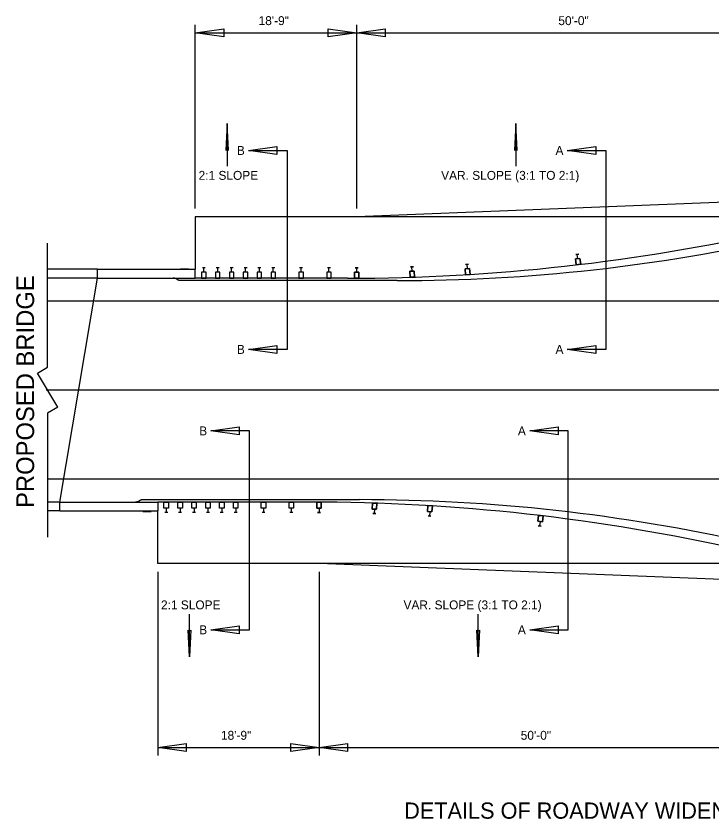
# Model space of a CAD drawing. Extents: x -149 to 1228740, y -106 to 152440.
# Drawn here: x -124.69 to -81.77, y -103.1 to -53.6 of the extents above; entities that cross this region are included whole.
import ezdxf

# ---------------------------------------------------------------- set-up
doc = ezdxf.new("R2010")
doc.units = 0
for name, color, linetype in [('B_Concrete', 7, 'Continuous'), ('R_Annotation', 7, 'Continuous'), ('R_Centerline', 7, 'Continuous'), ('R_Dimension', 7, 'Continuous'), ('R_Proposed Road', 7, 'Continuous'), ('R_Proposed Road_Lane', 7, 'Continuous'), ('R_Proposed Road_Shoulder', 7, 'Continuous')]:
    doc.layers.add(name, color=color, linetype=linetype)

msp = doc.modelspace()

# ---------------------------------------------------------------- linework, layer by layer
at = {"layer": 'B_Concrete'}
for p, q in [((-119.665, -69.21), (-122.739, -69.21)), ((-119.665, -69.21), (-113.633, -69.21)), ((-114.546, -69.181), (-114.044, -69.181)), ((-114.546, -69.181), (-114.546, -69.21)), ((-114.501, -69.181), (-114.501, -69.21)), ((-114.455, -69.181), (-114.455, -69.21)), ((-114.135, -69.181), (-114.135, -69.21)), ((-114.089, -69.181), (-114.089, -69.21)), ((-114.044, -69.181), (-114.044, -69.21)), ((-113.633, -69.758), (-113.633, -69.21)), ((-119.665, -69.758), (-122.739, -69.758)), ((-119.665, -69.758), (-113.633, -69.758)), ((-121.986, -83.56), (-122.739, -83.56)), ((-121.986, -83.56), (-115.953, -83.56)), ((-115.953, -83.56), (-115.953, -84.108)), ((-121.986, -84.108), (-122.739, -84.108)), ((-121.986, -84.108), (-115.953, -84.108)), ((-116.867, -84.137), (-116.867, -84.108)), ((-116.867, -84.137), (-116.364, -84.137)), ((-116.821, -84.137), (-116.821, -84.108)), ((-116.776, -84.137), (-116.776, -84.108)), ((-116.456, -84.137), (-116.456, -84.108)), ((-116.41, -84.137), (-116.41, -84.108)), ((-116.364, -84.137), (-116.364, -84.108))]:
    msp.add_line(p, q, dxfattribs=at)
for points in [[(-119.665, -69.758), (-119.665, -69.21)], [(-119.665, -69.758), (-119.665, -69.21)], [(-121.986, -83.56), (-119.665, -69.758)], [(-121.986, -84.108), (-121.986, -83.56)], [(-121.986, -84.108), (-121.986, -83.56)]]:
    msp.add_lwpolyline(points, dxfattribs=at)
at = {"layer": 'R_Annotation'}
for p, q in [((-111.675, -60.214), (-111.675, -62.856)), ((-93.874, -60.214), (-93.874, -62.856)), ((-122.739, -75.247), (-122.739, -67.588)), ((-123.361, -75.606), (-122.739, -75.247)), ((-122.117, -77.711), (-123.361, -75.606)), ((-122.117, -77.711), (-122.739, -78.07)), ((-122.739, -78.07), (-122.739, -85.73)), ((-113.996, -93.105), (-113.996, -90.463)), ((-96.195, -93.105), (-96.195, -90.463))]:
    msp.add_line(p, q, dxfattribs=at)
for points in [[(-111.675, -60.214), (-111.757, -61.859), (-111.675, -61.813), (-111.593, -61.859)], [(-93.874, -60.214), (-93.957, -61.859), (-93.874, -61.813), (-93.792, -61.859)], [(-113.996, -93.105), (-114.078, -91.459), (-113.996, -91.505), (-113.913, -91.459)], [(-96.195, -93.105), (-96.277, -91.459), (-96.195, -91.505), (-96.113, -91.459)]]:
    msp.add_lwpolyline(points, close=True, dxfattribs=at)
at = {"layer": 'R_Centerline'}
msp.add_line((-40.54, -76.659), (-122.83, -76.659), dxfattribs=at)
at = {"layer": 'R_Dimension'}
for p, q in [((-113.633, -65.465), (-113.633, -54.129)), ((-103.681, -65.465), (-103.681, -54.129)), ((-113.633, -54.629), (-103.681, -54.629)), ((-103.681, -54.629), (-76.262, -54.629)), ((-113.633, -61.99), (-113.633, -58.2)), ((-115.953, -87.853), (-115.953, -99.189)), ((-106.002, -87.853), (-106.002, -99.189)), ((-115.953, -92.394), (-115.953, -96.185)), ((-115.953, -98.689), (-106.002, -98.689)), ((-106.002, -98.689), (-78.582, -98.689))]:
    msp.add_line(p, q, dxfattribs=at)
for points in [[(-111.883, -54.879), (-113.633, -54.629), (-111.883, -54.379)], [(-105.431, -54.379), (-103.681, -54.629), (-105.431, -54.879)], [(-101.931, -54.879), (-103.681, -54.629), (-101.931, -54.379)], [(-108.602, -62.133), (-110.352, -61.883), (-108.602, -61.633)], [(-88.943, -62.133), (-90.693, -61.883), (-88.943, -61.633)], [(-108.602, -74.398), (-110.352, -74.148), (-108.602, -73.898)], [(-88.943, -74.398), (-90.693, -74.148), (-88.943, -73.898)], [(-110.923, -79.421), (-112.673, -79.171), (-110.923, -78.921)], [(-91.264, -79.421), (-93.014, -79.171), (-91.264, -78.921)], [(-110.923, -91.685), (-112.673, -91.435), (-110.923, -91.185)], [(-91.264, -91.685), (-93.014, -91.435), (-91.264, -91.185)], [(-114.203, -98.939), (-115.953, -98.689), (-114.203, -98.439)], [(-107.752, -98.439), (-106.002, -98.689), (-107.752, -98.939)], [(-104.252, -98.939), (-106.002, -98.689), (-104.252, -98.439)]]:
    msp.add_lwpolyline(points, close=True, dxfattribs=at)
for points in [[(-110.352, -61.883), (-107.972, -61.883), (-107.972, -74.148), (-110.352, -74.148)], [(-90.693, -61.883), (-88.312, -61.883), (-88.312, -74.148), (-90.693, -74.148)], [(-112.673, -91.435), (-110.292, -91.435), (-110.292, -79.171), (-112.673, -79.171)], [(-93.014, -91.435), (-90.633, -91.435), (-90.633, -79.171), (-93.014, -79.171)]]:
    msp.add_lwpolyline(points, dxfattribs=at)
at = {"layer": 'R_Proposed Road'}
for p, q in [((-89.989, -68.278), (-90.17, -68.3)), ((-90.17, -68.3), (-89.989, -68.278)), ((-90.048, -68.556), (-90.08, -68.289)), ((-90.048, -68.556), (-90.08, -68.289)), ((-114.501, -69.181), (-114.501, -69.21)), ((-114.455, -69.181), (-114.455, -69.21)), ((-114.135, -69.181), (-114.135, -69.21)), ((-114.089, -69.181), (-114.089, -69.21)), ((-113.016, -69.124), (-113.198, -69.124)), ((-113.107, -69.392), (-113.107, -69.124)), ((-112.159, -69.124), (-112.342, -69.124)), ((-112.25, -69.392), (-112.25, -69.124)), ((-111.302, -69.124), (-111.485, -69.124)), ((-111.393, -69.392), (-111.393, -69.124)), ((-110.445, -69.124), (-110.628, -69.124)), ((-110.536, -69.392), (-110.536, -69.124)), ((-109.588, -69.124), (-109.771, -69.124)), ((-109.68, -69.392), (-109.68, -69.124)), ((-108.731, -69.124), (-108.914, -69.124)), ((-108.823, -69.392), (-108.823, -69.124)), ((-107.018, -69.124), (-107.2, -69.124)), ((-107.109, -69.392), (-107.109, -69.124)), ((-105.304, -69.124), (-105.487, -69.124)), ((-105.395, -69.392), (-105.395, -69.124)), ((-103.59, -69.124), (-103.773, -69.124)), ((-103.59, -69.124), (-103.773, -69.124)), ((-103.773, -69.124), (-103.59, -69.124)), ((-103.681, -69.392), (-103.681, -69.124)), ((-103.681, -69.392), (-103.681, -69.124)), ((-103.681, -69.392), (-103.681, -69.124)), ((-100.185, -69.055), (-100.368, -69.062)), ((-100.368, -69.062), (-100.185, -69.055)), ((-100.267, -69.327), (-100.276, -69.058)), ((-100.267, -69.327), (-100.276, -69.058)), ((-96.779, -68.893), (-96.962, -68.904)), ((-96.962, -68.904), (-96.779, -68.893)), ((-96.854, -69.166), (-96.871, -68.898)), ((-96.854, -69.166), (-96.871, -68.898)), ((-89.868, -68.902), (-90.141, -68.935)), ((-90.141, -68.935), (-89.868, -68.902)), ((-104.241, -69.758), (-113.633, -69.758)), ((-112.97, -69.758), (-113.244, -69.758)), ((-112.113, -69.758), (-112.387, -69.758)), ((-111.256, -69.758), (-111.53, -69.758)), ((-110.399, -69.758), (-110.673, -69.758)), ((-109.542, -69.758), (-109.817, -69.758)), ((-108.686, -69.758), (-108.96, -69.758)), ((-106.972, -69.758), (-107.246, -69.758)), ((-105.258, -69.758), (-105.532, -69.758)), ((-103.544, -69.758), (-103.819, -69.758)), ((-103.544, -69.758), (-103.819, -69.758)), ((-103.819, -69.758), (-103.544, -69.758)), ((-100.118, -69.688), (-100.392, -69.697)), ((-100.392, -69.697), (-100.118, -69.688)), ((-96.694, -69.523), (-96.968, -69.54)), ((-96.968, -69.54), (-96.694, -69.523)), ((-101.19, -69.906), (-114.51, -69.906)), ((-103.511, -83.412), (-116.831, -83.412)), ((-106.562, -83.56), (-115.953, -83.56)), ((-115.291, -83.56), (-115.565, -83.56)), ((-114.434, -83.56), (-114.708, -83.56)), ((-113.577, -83.56), (-113.851, -83.56)), ((-112.72, -83.56), (-112.994, -83.56)), ((-111.863, -83.56), (-112.137, -83.56)), ((-111.006, -83.56), (-111.28, -83.56)), ((-109.293, -83.56), (-109.567, -83.56)), ((-107.579, -83.56), (-107.853, -83.56)), ((-105.865, -83.56), (-106.139, -83.56)), ((-105.865, -83.56), (-106.139, -83.56)), ((-106.139, -83.56), (-105.865, -83.56)), ((-102.438, -83.631), (-102.712, -83.621)), ((-102.712, -83.621), (-102.438, -83.631)), ((-115.428, -83.926), (-115.428, -84.195)), ((-114.571, -83.926), (-114.571, -84.195)), ((-113.714, -83.926), (-113.714, -84.195)), ((-112.857, -83.926), (-112.857, -84.195)), ((-112, -83.926), (-112, -84.195)), ((-111.143, -83.926), (-111.143, -84.195)), ((-109.43, -83.926), (-109.43, -84.195)), ((-107.716, -83.926), (-107.716, -84.195)), ((-106.002, -83.926), (-106.002, -84.195)), ((-106.002, -83.926), (-106.002, -84.195)), ((-106.002, -83.926), (-106.002, -84.195)), ((-102.588, -83.991), (-102.597, -84.26)), ((-102.588, -83.991), (-102.597, -84.26)), ((-99.015, -83.796), (-99.289, -83.779)), ((-99.289, -83.779), (-99.015, -83.796)), ((-115.336, -84.195), (-115.519, -84.195)), ((-114.479, -84.195), (-114.662, -84.195)), ((-113.623, -84.195), (-113.805, -84.195)), ((-112.766, -84.195), (-112.948, -84.195)), ((-111.909, -84.195), (-112.092, -84.195)), ((-111.052, -84.195), (-111.235, -84.195)), ((-109.338, -84.195), (-109.521, -84.195)), ((-107.624, -84.195), (-107.807, -84.195)), ((-105.911, -84.195), (-106.094, -84.195)), ((-105.911, -84.195), (-106.094, -84.195)), ((-106.094, -84.195), (-105.911, -84.195)), ((-102.506, -84.263), (-102.688, -84.257)), ((-102.688, -84.257), (-102.506, -84.263)), ((-99.1, -84.426), (-99.282, -84.414)), ((-99.282, -84.414), (-99.1, -84.426)), ((-99.175, -84.152), (-99.191, -84.42)), ((-99.175, -84.152), (-99.191, -84.42)), ((-92.189, -84.416), (-92.461, -84.383)), ((-92.461, -84.383), (-92.189, -84.416)), ((-92.31, -85.04), (-92.491, -85.018)), ((-92.491, -85.018), (-92.31, -85.04)), ((-92.368, -84.762), (-92.4, -85.029)), ((-92.368, -84.762), (-92.4, -85.029))]:
    msp.add_line(p, q, dxfattribs=at)
for points in [[(-40.54, -64.89), (-76.262, -64.89), (-103.681, -65.965)], [(-40.54, -88.428), (-78.582, -88.428), (-106.002, -87.353)]]:
    msp.add_lwpolyline(points, dxfattribs=at)
for points in [[(-90.141, -68.935), (-89.868, -68.902), (-89.912, -68.539), (-90.184, -68.572)], [(-89.868, -68.902), (-90.141, -68.935), (-90.184, -68.572), (-89.912, -68.539)], [(-96.968, -69.54), (-96.694, -69.523), (-96.717, -69.158), (-96.991, -69.175)], [(-96.694, -69.523), (-96.968, -69.54), (-96.991, -69.175), (-96.717, -69.158)], [(-113.244, -69.758), (-112.97, -69.758), (-112.97, -69.392), (-113.244, -69.392)], [(-112.387, -69.758), (-112.113, -69.758), (-112.113, -69.392), (-112.387, -69.392)], [(-111.53, -69.758), (-111.256, -69.758), (-111.256, -69.392), (-111.53, -69.392)], [(-110.673, -69.758), (-110.399, -69.758), (-110.399, -69.392), (-110.673, -69.392)], [(-109.817, -69.758), (-109.542, -69.758), (-109.542, -69.392), (-109.817, -69.392)], [(-108.96, -69.758), (-108.686, -69.758), (-108.686, -69.392), (-108.96, -69.392)], [(-107.246, -69.758), (-106.972, -69.758), (-106.972, -69.392), (-107.246, -69.392)], [(-105.532, -69.758), (-105.258, -69.758), (-105.258, -69.392), (-105.532, -69.392)], [(-103.819, -69.758), (-103.544, -69.758), (-103.544, -69.392), (-103.819, -69.392)], [(-103.819, -69.758), (-103.544, -69.758), (-103.544, -69.392), (-103.819, -69.392)], [(-103.544, -69.758), (-103.819, -69.758), (-103.819, -69.392), (-103.544, -69.392)], [(-100.392, -69.697), (-100.118, -69.688), (-100.13, -69.322), (-100.404, -69.331)], [(-100.118, -69.688), (-100.392, -69.697), (-100.404, -69.331), (-100.13, -69.322)], [(-115.565, -83.56), (-115.291, -83.56), (-115.291, -83.926), (-115.565, -83.926)], [(-114.708, -83.56), (-114.434, -83.56), (-114.434, -83.926), (-114.708, -83.926)], [(-113.851, -83.56), (-113.577, -83.56), (-113.577, -83.926), (-113.851, -83.926)], [(-112.994, -83.56), (-112.72, -83.56), (-112.72, -83.926), (-112.994, -83.926)], [(-112.137, -83.56), (-111.863, -83.56), (-111.863, -83.926), (-112.137, -83.926)], [(-111.28, -83.56), (-111.006, -83.56), (-111.006, -83.926), (-111.28, -83.926)], [(-109.567, -83.56), (-109.293, -83.56), (-109.293, -83.926), (-109.567, -83.926)], [(-107.853, -83.56), (-107.579, -83.56), (-107.579, -83.926), (-107.853, -83.926)], [(-106.139, -83.56), (-105.865, -83.56), (-105.865, -83.926), (-106.139, -83.926)], [(-106.139, -83.56), (-105.865, -83.56), (-105.865, -83.926), (-106.139, -83.926)], [(-105.865, -83.56), (-106.139, -83.56), (-106.139, -83.926), (-105.865, -83.926)], [(-102.712, -83.621), (-102.438, -83.631), (-102.451, -83.996), (-102.725, -83.987)], [(-102.438, -83.631), (-102.712, -83.621), (-102.725, -83.987), (-102.451, -83.996)], [(-99.289, -83.779), (-99.015, -83.796), (-99.038, -84.161), (-99.311, -84.143)], [(-99.015, -83.796), (-99.289, -83.779), (-99.311, -84.143), (-99.038, -84.161)], [(-92.461, -84.383), (-92.189, -84.416), (-92.232, -84.779), (-92.505, -84.746)], [(-92.189, -84.416), (-92.461, -84.383), (-92.505, -84.746), (-92.232, -84.779)]]:
    msp.add_lwpolyline(points, close=True, dxfattribs=at)
for centre, radius, start, end in [((-104.241, 51.438), 121.196, 270, 282.67799), ((-101.19, 39.773), 109.68, 270, 282.67799), ((-106.562, -204.756), 121.196, 77.32201, 90), ((-103.511, -193.091), 109.68, 77.32201, 90)]:
    msp.add_arc(centre, radius, start, end, dxfattribs=at)
for points in [[(-114.51, -69.906), (-114.677, -69.906), (-114.837, -69.759), (-115.004, -69.758)], [(-116.831, -83.412), (-116.998, -83.412), (-117.158, -83.559), (-117.324, -83.56)]]:
    msp.add_open_spline(points, degree=2, dxfattribs=at)
at = {"layer": 'R_Proposed Road_Lane'}
msp.add_line((-119.95, -71.175), (-122.739, -71.175), dxfattribs=at)
for points in [[(-40.54, -71.175), (-50.279, -71.175), (-51.306, -71.175), (-59.602, -71.175), (-62.717, -71.175), (-90.137, -71.175), (-96.257, -71.175), (-96.893, -71.175), (-119.858, -71.175)], [(-40.54, -82.143), (-46.457, -82.143), (-47.484, -82.143), (-55.78, -82.143), (-58.895, -82.143), (-86.314, -82.143), (-92.435, -82.143), (-93.071, -82.143), (-122.739, -82.143)]]:
    msp.add_lwpolyline(points, dxfattribs=at)
at = {"layer": 'R_Proposed Road_Shoulder'}
for points in [[(-48.02, -69.758), (-70.778, -65.965), (-113.633, -65.965), (-113.633, -69.21)], [(-50.339, -83.56), (-73.098, -87.353), (-115.953, -87.353), (-115.953, -84.108)]]:
    msp.add_lwpolyline(points, dxfattribs=at)

# ---------------------------------------------------------------- texts
at = {"layer": 'R_Annotation'}
for s, height, p in [('18\'-9"', 0.55, (-109.733, -54.154)), ('50\'-0"', 0.55, (-91.247, -54.154)), ('B', 0.548, (-111.071, -62.157)), ('A', 0.548, (-91.42, -62.157)), ('2:1 SLOPE', 0.5484, (-113.429, -63.692)), ('VAR. SLOPE (3:1 TO 2:1)', 0.5484, (-98.473, -63.692)), ('B', 0.548, (-111.071, -74.422)), ('A', 0.548, (-91.42, -74.422)), ('B', 0.548, (-113.392, -79.445)), ('A', 0.548, (-93.741, -79.445)), ('2:1 SLOPE', 0.5484, (-115.749, -90.174)), ('VAR. SLOPE (3:1 TO 2:1)', 0.5484, (-100.794, -90.174)), ('B', 0.548, (-113.392, -91.709)), ('B', 0.548, (-113.392, -91.709)), ('A', 0.548, (-93.741, -91.709)), ('18\'-9"', 0.55, (-112.054, -98.214)), ('50\'-0"', 0.55, (-93.568, -98.214)), ('DETAILS OF ROADWAY WIDENING FOR GUARDRAIL', 1, (-100.754, -103.081))]:
    msp.add_text(s, height=height, dxfattribs=at).set_placement(p)
msp.add_text('PROPOSED BRIDGE', height=1.0968, rotation=90, dxfattribs=at).set_placement((-123.575, -83.922))
at = {"layer": 'R_Dimension'}
msp.add_text('A', height=0.548, dxfattribs=at).set_placement((-93.741, -91.709))

doc.saveas('drawing.dxf')
